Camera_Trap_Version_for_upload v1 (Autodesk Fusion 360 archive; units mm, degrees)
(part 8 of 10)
sketch "Sketch7" plane through (-24, 0, 0) normal (-1, 0, 0) x axis (0, -1, 0)
  line L1 (-21.6307, 110.325) -> (-21.6307, 118.7956)
  line L2 (-42.326, 110.325) -> (-21.6307, 110.325)
  line L3 (-42.326, 118.7956) -> (-42.326, 110.325)
  line L4 (-21.6307, 118.7956) -> (-42.326, 118.7956)
  line L5 (-18.3395, 176) -> (-20.9219, 176)
  line L6 (-44.3395, 176) -> (-46.9219, 176)
  curve K1 (35.395, 253.2053) -> (39.3474, 235.851)
  line L7 (-53, 253.2053) -> (35.395, 253.2053)
  line L8 (-53, 28) -> (-53, 253.2053)
  line L9 (-33, 28) -> (-53, 28)
  line L10 (-2.8201, 28) -> (-33, 28)
  line L11 (-35, 194) -> (-35, 213)
  line L12 (-42, 194) -> (-35, 194)
  line L13 (-42, 213) -> (-42, 194)
  line L14 (-35, 213) -> (-42, 213)
  arc A1 centre (-19.6307, 176.5411) radius 1.4 clockwise from (-18.3395, 176) to (-20.9219, 176)
  arc A2 centre (-45.6307, 176.5411) radius 1.4 clockwise from (-44.3395, 176) to (-46.9219, 176)
  circle C1 centre (-19.6307, 107.155) radius 1.4
  circle C2 centre (-45.6307, 107.155) radius 1.4
  arc A3 centre (-2.8201, 80) radius 52 clockwise from (40.4895, 108.7798) to (-2.8201, 28)
  arc A4 centre (82.1333, 136.4527) radius 50 clockwise from (40.4895, 108.7798) to (32.1436, 135.4388)
  arc A5 centre (1.7685, 134.8228) radius 30.3814 clockwise from (31.815, 139.3208) to (32.1436, 135.4388)
  arc A6 centre (81.264, 146.7234) radius 50 clockwise from (31.815, 139.3208) to (40.632, 175.8617)
  arc A7 centre (0, 205) radius 50 clockwise from (39.3474, 235.851) to (40.632, 175.8617)
extrude "Extrude18" add sketch "Sketch7" profile of L1 L2 L3 L4 against normal blind 5
extrude "Extrude19" add of existing geometry blind 6
extrude "Extrude20" add of existing geometry blind 2
move "Move1"
sketch "Sketch8" plane through (-24, 0, 0) normal (-1, 0, 0) x axis (0, -1, 0)
  line L1 (-18.3395, 176) -> (-20.9219, 176)
  line L2 (-44.3395, 176) -> (-46.9219, 176)
  curve K1 (35.395, 253.2053) -> (39.3474, 235.851)
  line L3 (-53, 253.2053) -> (35.395, 253.2053)
  line L4 (-53, 28) -> (-53, 253.2053)
  line L5 (-33, 28) -> (-53, 28)
  line L6 (-2.8201, 28) -> (-33, 28)
  line L7 (-35, 194) -> (-35, 213)
  line L8 (-42, 194) -> (-35, 194)
  line L9 (-42, 213) -> (-42, 194)
  line L10 (-35, 213) -> (-42, 213)
  line L11 (-14.5, 105.4339) -> (-50.5, 105.4339)
  line L12 (-50.5, 176) -> (-50.5, 105.4339)
  line L13 (-14.5, 176) -> (-50.5, 176)
  line L14 (-14.5, 105.4339) -> (-14.5, 176)
  curve K2 (-25.2655, 144.5781) -> (-27.9943, 141.8305)
  line L15 (-25.2773, 147.9781) -> (-25.2655, 144.5781)
  curve K3 (-28.0249, 150.7069) -> (-25.2773, 147.9781)
  line L16 (-31.5199, 150.6948) -> (-28.0249, 150.7069)
  curve K4 (-34.2486, 147.9471) -> (-31.5199, 150.6948)
  line L17 (-34.2369, 144.5472) -> (-34.2486, 147.9471)
  curve K5 (-31.4893, 141.8184) -> (-34.2369, 144.5472)
  line L18 (-27.9943, 141.8305) -> (-31.4893, 141.8184)
  curve K6 (-25.2925, 156.805) -> (-28.0307, 154.0668)
  line L19 (-25.2925, 160.205) -> (-25.2925, 156.805)
  curve K7 (-28.0307, 162.9432) -> (-25.2925, 160.205)
  line L20 (-31.5257, 162.9432) -> (-28.0307, 162.9432)
  curve K8 (-34.2639, 160.205) -> (-31.5257, 162.9432)
  line L21 (-34.2639, 156.805) -> (-34.2639, 160.205)
  curve K9 (-31.5257, 154.0668) -> (-34.2639, 156.805)
  line L22 (-28.0307, 154.0668) -> (-31.5257, 154.0668)
  arc A1 centre (-19.6307, 176.5411) radius 1.4 clockwise from (-18.3395, 176) to (-20.9219, 176)
  arc A2 centre (-45.6307, 176.5411) radius 1.4 clockwise from (-44.3395, 176) to (-46.9219, 176)
  arc A3 centre (-2.8201, 80) radius 52 clockwise from (40.4895, 108.7798) to (-2.8201, 28)
  arc A4 centre (82.1333, 136.4527) radius 50 clockwise from (40.4895, 108.7798) to (32.1436, 135.4388)
  arc A5 centre (1.7685, 134.8228) radius 30.3814 clockwise from (31.815, 139.3208) to (32.1436, 135.4388)
  arc A6 centre (81.264, 146.7234) radius 50 clockwise from (31.815, 139.3208) to (40.632, 175.8617)
  arc A7 centre (0, 205) radius 50 clockwise from (39.3474, 235.851) to (40.632, 175.8617)
move "Move2"
sketch "Sketch9" plane through (-24, 0, 0) normal (-1, 0, 0) x axis (0, -1, 0)
  line L1 (-18.3395, 176) -> (-20.9219, 176)
  line L2 (-44.3395, 176) -> (-46.9219, 176)
  curve K1 (35.395, 253.2053) -> (39.3474, 235.851)
  line L3 (-53, 253.2053) -> (35.395, 253.2053)
  line L4 (-53, 28) -> (-53, 253.2053)
  line L5 (-33, 28) -> (-53, 28)
  line L6 (-2.8201, 28) -> (-33, 28)
  line L7 (-35, 194) -> (-35, 213)
  line L8 (-42, 194) -> (-35, 194)
  line L9 (-42, 213) -> (-42, 194)
  line L10 (-35, 213) -> (-42, 213)
  line L11 (-14.5, 105.4339) -> (-14.5, 176)
  line L12 (-14.5, 176) -> (-50.5, 176)
  line L13 (-50.5, 176) -> (-50.5, 105.4339)
  line L14 (-14.5, 105.4339) -> (-50.5, 105.4339)
  arc A1 centre (-19.6307, 176.5411) radius 1.4 clockwise from (-18.3395, 176) to (-20.9219, 176)
  arc A2 centre (-45.6307, 176.5411) radius 1.4 clockwise from (-44.3395, 176) to (-46.9219, 176)
  arc A3 centre (-2.8201, 80) radius 52 clockwise from (40.4895, 108.7798) to (-2.8201, 28)
  arc A4 centre (82.1333, 136.4527) radius 50 clockwise from (40.4895, 108.7798) to (32.1436, 135.4388)
  arc A5 centre (1.7685, 134.8228) radius 30.3814 clockwise from (31.815, 139.3208) to (32.1436, 135.4388)
  arc A6 centre (81.264, 146.7234) radius 50 clockwise from (31.815, 139.3208) to (40.632, 175.8617)
  arc A7 centre (0, 205) radius 50 clockwise from (39.3474, 235.851) to (40.632, 175.8617)
extrude "Extrude21" cut sketch "Sketch2" against normal blind 3
sketch "Sketch10" plane through (-24, 0, 0) normal (-1, 0, 0) x axis (0, -1, 0)
  line L1 (-49, 173) -> (-49, 116.4339)
  line L2 (-16, 173) -> (-49, 173)
  line L3 (-16, 116.4339) -> (-16, 173)
  line L4 (-49, 116.4339) -> (-16, 116.4339)
  line L5 (-18.3395, 176) -> (-20.9219, 176)
  line L6 (-44.3395, 176) -> (-46.9219, 176)
  curve K1 (35.395, 253.2053) -> (39.3474, 235.851)
  line L7 (-53, 253.2053) -> (35.395, 253.2053)
  line L8 (-53, 28) -> (-53, 253.2053)
  line L9 (-33, 28) -> (-53, 28)
  line L10 (-2.8201, 28) -> (-33, 28)
  line L11 (-35, 194) -> (-35, 213)
  line L12 (-42, 194) -> (-35, 194)
  line L13 (-42, 213) -> (-42, 194)
  line L14 (-35, 213) -> (-42, 213)
  line L15 (-11.1732, 178.4668) -> (-50.2813, 178.4668)
  line L16 (-11.1732, 173) -> (-11.1732, 178.4668)
  line L17 (-50.2813, 173) -> (-11.1732, 173)
  line L18 (-50.2813, 178.4668) -> (-50.2813, 173)
  arc A1 centre (-19.6307, 176.5411) radius 1.4 clockwise from (-18.3395, 176) to (-20.9219, 176)
  arc A2 centre (-45.6307, 176.5411) radius 1.4 clockwise from (-44.3395, 176) to (-46.9219, 176)
  arc A3 centre (-2.8201, 80) radius 52 clockwise from (40.4895, 108.7798) to (-2.8201, 28)
  arc A4 centre (82.1333, 136.4527) radius 50 clockwise from (40.4895, 108.7798) to (32.1436, 135.4388)
  arc A5 centre (1.7685, 134.8228) radius 30.3814 clockwise from (31.815, 139.3208) to (32.1436, 135.4388)
  arc A6 centre (81.264, 146.7234) radius 50 clockwise from (31.815, 139.3208) to (40.632, 175.8617)
  arc A7 centre (0, 205) radius 50 clockwise from (39.3474, 235.851) to (40.632, 175.8617)
  horizontal L15
  vertical L16
  horizontal L17
  vertical L18
extrude "Extrude22" add of existing geometry blind 6
offset_faces "OffsetFaces2" distance -0.3
sketch "Sketch11" plane through (-24, 0, 0) normal (-1, 0, 0) x axis (0, -1, 0)
  line L1 (-35, 194) -> (-35, 213)
  line L2 (-42, 194) -> (-35, 194)
  line L3 (-42, 213) -> (-42, 194)
  line L4 (-35, 213) -> (-42, 213)
  curve K1 (35.395, 253.2053) -> (39.3474, 235.851)
  line L5 (-53, 253.2053) -> (35.395, 253.2053)
  line L6 (-53, 28) -> (-53, 253.2053)
  line L7 (-33, 28) -> (-53, 28)
  line L8 (-2.8201, 28) -> (-33, 28)
  line L9 (-49.3, 173.3) -> (-49.3, 116.1339)
  line L10 (-15.7, 173.3) -> (-49.3, 173.3)
  line L11 (-15.7, 116.1339) -> (-15.7, 173.3)
  line L12 (-49.3, 116.1339) -> (-15.7, 116.1339)
  line L13 (-41, 110.4339) -> (-22, 110.4339)
  line L14 (-22, 116.4339) -> (-22, 110.4339)
  line L15 (-41, 116.4339) -> (-41, 110.4339)
  line L16 (-21.9927, 116.4339) -> (-41, 116.4339)
  line L17 (-21.9927, 107.685) -> (-21.9927, 116.4339)
  line L18 (-41, 107.685) -> (-21.9927, 107.685)
  line L19 (-41, 116.4339) -> (-41, 107.685)
  arc A1 centre (-2.8201, 80) radius 52 clockwise from (40.4895, 108.7798) to (-2.8201, 28)
  arc A2 centre (82.1333, 136.4527) radius 50 clockwise from (40.4895, 108.7798) to (32.1436, 135.4388)
  arc A3 centre (1.7685, 134.8228) radius 30.3814 clockwise from (31.815, 139.3208) to (32.1436, 135.4388)
  arc A4 centre (81.264, 146.7234) radius 50 clockwise from (31.815, 139.3208) to (40.632, 175.8617)
  arc A5 centre (0, 205) radius 50 clockwise from (39.3474, 235.851) to (40.632, 175.8617)
  point P28 (-41, 116.4339)
  point P29 (-41, 116.4339)
  horizontal L16
  vertical L17
  horizontal L18
  vertical L19
  coincident P28 P29
extrude "Extrude23" cut sketch "Sketch11" profile of L12 L13 L14 L15 L17 L18 L19 to an object
move "Move3"
extrude "Extrude24" cut sketch "Sketch8" + "Sketch6" + "Sketch10" profile of S2:C1 S1:A1 S1:A2 S1:L11 S1:L12 S1:L13 S1:L14 S1:K2 S1:L15 S1:K3 S1:L16 S1:K4 S1:L17 S1:K5 S1:L18 S1:K6 S1:L19 S1:K7 S1:L20 S1:K8 S1:L21 S1:K9 S1:L22 S3:A2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 blind -3
extrude "Extrude25" cut of existing geometry to an object
extrude "Extrude26" cut of existing geometry to an object
sketch "Sketch12" plane through (-24, 0, 0) normal (-1, 0, 0) x axis (0, -1, 0)
  line L1 (-14.5, 105.4339) -> (-14.5, 176)
  line L2 (-50.5, 105.4339) -> (-14.5, 105.4339)
  line L3 (-50.5, 176) -> (-50.5, 105.4339)
  line L4 (-20.9219, 176) -> (-50.5, 176)
  line L5 (-14.5, 176) -> (-18.3395, 176)
  line L6 (-35, 194) -> (-35, 213)
  line L7 (-42, 194) -> (-35, 194)
  line L8 (-42, 213) -> (-42, 194)
  line L9 (-35, 213) -> (-42, 213)
  curve K1 (35.395, 253.2053) -> (39.3474, 235.851)
  line L10 (-53, 253.2053) -> (35.395, 253.2053)
  line L11 (-53, 28) -> (-53, 253.2053)
  line L12 (-33, 28) -> (-53, 28)
  line L13 (-2.8201, 28) -> (-33, 28)
  line L14 (-18.3395, 176) -> (-20.9219, 176)
  arc A1 centre (-19.6307, 176.5411) radius 1.4 clockwise from (-18.3395, 176) to (-20.9219, 176)
  arc A2 centre (-2.8201, 80) radius 52 clockwise from (40.4895, 108.7798) to (-2.8201, 28)
  arc A3 centre (82.1333, 136.4527) radius 50 clockwise from (40.4895, 108.7798) to (32.1436, 135.4388)
  arc A4 centre (1.7685, 134.8228) radius 30.3814 clockwise from (31.815, 139.3208) to (32.1436, 135.4388)
  arc A5 centre (81.264, 146.7234) radius 50 clockwise from (31.815, 139.3208) to (40.632, 175.8617)
  arc A6 centre (0, 205) radius 50 clockwise from (39.3474, 235.851) to (40.632, 175.8617)
  point P6 (-20.9219, 176)
  point P28 (-20.9219, 176)
  point P7 (-18.3395, 176)
  point P29 (-18.3395, 176)
  coincident P6 P28
  coincident P7 P29
extrude "Extrude27" cut sketch "Sketch12" profile of A1 L14 against normal blind 3
extrude "Extrude28" cut of existing geometry blind -1
extrude "Extrude29" cut of existing geometry blind -1
extrude "Extrude24" cut of existing geometry blind -3
fillet "Fillet1" radius 1
fillet "Fillet2" radius 1
fillet "Fillet3" radius 1
fillet "Fillet4" radius 1
fillet "Fillet1" radius 1
fillet "Fillet2" radius 1
fillet "Fillet3" radius 1
fillet "Fillet4" radius 1
extrude "Extrude24" cut of existing geometry to an object
extrude "Extrude25" cut of existing geometry blind -1
combine "Combine5"
sketch "Sketch33" plane through (-28.991, 0, 0) normal (-1, 0, 0) x axis (0, -1, 0)
  line L1 (-15.5, 105.4339) -> (-49.5, 105.4339)
  line L2 (-14.5, 175) -> (-14.5, 106.4339)
  line L3 (-49.5, 176) -> (-15.5, 176)
  line L4 (-50.5, 106.4339) -> (-50.5, 175)
  line L5 (-31.5257, 154.0668) -> (-28.0307, 154.0668)
  curve K1 (-34.2639, 156.805) -> (-31.5257, 154.0668)
  line L6 (-34.2639, 160.205) -> (-34.2639, 156.805)
  curve K2 (-31.5257, 162.9432) -> (-34.2639, 160.205)
  line L7 (-28.0307, 162.9432) -> (-31.5257, 162.9432)
  curve K3 (-25.2925, 160.205) -> (-28.0307, 162.9432)
  line L8 (-25.2925, 156.805) -> (-25.2925, 160.205)
  curve K4 (-28.0307, 154.0668) -> (-25.2925, 156.805)
  line L9 (-31.4893, 141.8184) -> (-27.9943, 141.8305)
  curve K5 (-34.2369, 144.5472) -> (-31.4893, 141.8184)
  line L10 (-34.2486, 147.9471) -> (-34.2369, 144.5472)
  curve K6 (-31.5199, 150.6948) -> (-34.2486, 147.9471)
  line L11 (-28.0249, 150.7069) -> (-31.5199, 150.6948)
  curve K7 (-25.2773, 147.9781) -> (-28.0249, 150.7069)
  line L12 (-25.2655, 144.5781) -> (-25.2773, 147.9781)
  curve K8 (-27.9943, 141.8305) -> (-25.2655, 144.5781)
  line L13 (-32.5, 105.4339) -> (-32.5, 176)
  line L14 (-50.5, 140.7169) -> (-14.5, 140.7169)
  arc A1 centre (-49.5, 106.4339) radius 1 clockwise from (-49.5, 105.4339) to (-50.5, 106.4339)
  arc A2 centre (-15.5, 106.4339) radius 1 clockwise from (-14.5, 106.4339) to (-15.5, 105.4339)
  arc A3 centre (-15.5, 175) radius 1 clockwise from (-15.5, 176) to (-14.5, 175)
  arc A4 centre (-49.5, 175) radius 1 clockwise from (-50.5, 175) to (-49.5, 176)
  circle C1 centre (-47, 109) radius 1
  circle C2 centre (-18, 109) radius 1
  circle C3 centre (-47, 172.4339) radius 1
  circle C4 centre (-18, 172.4339) radius 1
  point P30 (-32.5, 176)
  point P31 (-32.5, 105.4339)
  point P32 (-14.5, 140.7169)
  point P33 (-50.5, 140.7169)
  point P34 (-47, 109)
  point P36 (-47, 172.4339)
  point P37 (-47, 172.4339)
  midpoint L3 P30
  midpoint L1 P31
  midpoint L2 P32
  midpoint L4 P33
  symmetric L13 C1 C2
  symmetric L14 P34 P36
  coincident P36 P37
  symmetric L13 C3 C4
  dimension "d1688" diameter C1 = 2
  dimension "d1689" diameter C3 = 2
extrude "Extrude30" cut sketch "Sketch33" profile of C1 C2 C3 C4 against normal blind 9
sketch "Sketch34" plane through (-17, 0, 0) normal (1, 0, 0) x axis (0, 1, 0)
  line L1 (33, 28) -> (2.8201, 28)
  line L2 (53, 28) -> (33, 28)
  line L3 (53, 253.2053) -> (53, 28)
  line L4 (-35.395, 253.2053) -> (53, 253.2053)
  curve K1 (-35.395, 253.2053) -> (-39.3474, 235.851)
  line L5 (13.4103, 132.8522) -> (13.4103, 142.8522)
  line L6 (-11.9897, 142.8522) -> (-11.9897, 132.8522)
  line L7 (35, 213) -> (35, 194)
  line L8 (42, 213) -> (35, 213)
  line L9 (42, 194) -> (42, 213)
  line L10 (35, 194) -> (42, 194)
  line L11 (41, 105.685) -> (41, 116.1339)
  line L12 (21.9927, 105.685) -> (41, 105.685)
  line L13 (21.9927, 116.1339) -> (21.9927, 105.685)
  line L14 (41, 116.1339) -> (21.9927, 116.1339)
  circle C1 centre (-38.4779, 196.3786) radius 5.075
  circle C2 centre (-38.4779, 86.3786) radius 5.075
  circle C3 centre (0.7043, 203.169) radius 13.1
  arc A1 centre (2.8201, 80) radius 52 clockwise from (2.8201, 28) to (-40.4895, 108.7798)
  arc A2 centre (0, 205) radius 50 clockwise from (-40.632, 175.8617) to (-39.3474, 235.851)
  arc A3 centre (-81.264, 146.7234) radius 50 clockwise from (-40.632, 175.8617) to (-31.815, 139.3208)
  arc A4 centre (-1.7685, 134.8228) radius 30.3814 clockwise from (-32.1436, 135.4388) to (-31.815, 139.3208)
  arc A5 centre (-82.1333, 136.4527) radius 50 clockwise from (-32.1436, 135.4388) to (-40.4895, 108.7798)
  circle C4 centre (51, 205) radius 1.5
  circle C5 centre (0.6307, 70.355) radius 13.1
  arc A6 centre (0.7103, 132.8522) radius 12.7 clockwise from (13.4103, 132.8522) to (-11.9897, 132.8522)
  arc A7 centre (0.7103, 142.8522) radius 12.7 clockwise from (-11.9897, 142.8522) to (13.4103, 142.8522)
combine "Combine1" bodies "Back_wall"
offset_faces "OffsetFaces1" distance 20
sketch "Sketch1" plane through (0, 53, 0) normal (0, -1, 0) x axis (1, 0, 0)
  line L1 (-17, 285.3985) -> (77.3814, 285.3985)
  line L2 (-17, 253.2053) -> (-17, 285.3985)
  line L3 (-24, 253.2053) -> (-17, 253.2053)
  line L4 (-24, 253.2048) -> (-24, 253.2053)
  line L5 (77.3814, 253.2048) -> (-24, 253.2048)
  line L6 (77.3814, 285.3985) -> (77.3814, 253.2048)
  line L7 (60.8674, 243.2048) -> (60.8674, 253.2048)
  line L8 (49.8805, 243.2048) -> (49.8805, 253.2048)
  circle C1 centre (55.374, 243.2048) radius 5.4934
  circle C2 centre (55.374, 243.2048) radius 1.5
  point P8 (60.8674, 253.2048)
  point P10 (49.8805, 253.2048)
  point P11 (49.8805, 243.2048)
  point P9 (60.8674, 243.2048)
  coincident L5 P8
  perpendicular L5 L7
  coincident L5 P10
  perpendicular L5 L8
  coincident P11 C1
  tangent L8 C1
  coincident P9 C1
  concentric C1 C2
  dimension "d1697" distance P8 P9 = 10
  dimension "d1698" distance P10 P11 = 10
  dimension "d1699" diameter C2 = 3
extrude "Extrude1" new body sketch "Sketch1" profile of L5 L7 L8 C1 C2 along normal blind 2
offset_faces "OffsetFaces2" distance 1
draft "Draft1" Angle1 40 Angle2 0
combine "Combine1"
sketch "Sketch2" plane through (125, 0, 0) normal (-1, 0, 0) x axis (0, -1, 0)
  line L1 (-53, 253.2053) -> (-53, 285.3985)
  line L2 (65.2611, 253.2053) -> (-53, 253.2053)
  line L3 (-53, 285.3985) -> (65.2611, 253.2053)
  line L4 (-4.7389, 253.2053) -> (65.2611, 253.2053)
  line L5 (-4.7389, 243.2053) -> (-4.7389, 253.2053)
  line L6 (-13.6775, 243.2053) -> (-13.6775, 253.2053)
  circle C1 centre (-6.6916, 266.9657) radius 3.15
  circle C2 centre (-9.2082, 243.2053) radius 4.4693
  circle C3 centre (-9.2082, 243.2053) radius 1.5
  point P4 (65.2611, 253.2053)
  point P6 (65.2611, 253.2053)
  point P9 (-13.6775, 253.2053)
  point P10 (-13.6775, 243.2053)
  point P8 (-4.7389, 243.2053)
  point P7 (-4.7389, 253.2053)
  coincident P4 P6
  parallel L2 L4
  perpendicular L2 L5
  coincident L2 P9
  perpendicular L2 L6
  coincident P10 C2
  tangent L6 C2
  coincident P8 C2
  concentric C2 C3
  dimension "d1705" distance P6 P7 = 70
  dimension "d1706" distance P7 P8 = 10
  dimension "d1707" distance P9 P10 = 10
  dimension "d1708" diameter C3 = 3
extrude "Extrude2" new body sketch "Sketch2" profile of L2 L5 L6 C2 C3 along normal blind 2
draft "Draft2" Angle1 45 Angle2 0
combine "Combine2"
sketch "Sketch3" plane through (-17, 0, 0) normal (1, 0, 0) x axis (0, 1, 0)
  line L1 (53, 253.2053) -> (-65.2611, 253.2053)
  line L2 (53, 285.3985) -> (53, 253.2053)
  line L3 (-65.2611, 253.2053) -> (53, 285.3985)
  line L4 (4.7389, 253.2053) -> (-65.2611, 253.2053)
  line L5 (4.7389, 243.2053) -> (4.7389, 253.2053)
  line L6 (4.7389, 253.2053) -> (13.6775, 253.2053)
  line L7 (4.7389, 243.2053) -> (4.7389, 253.2053)
  line L8 (13.6775, 253.2053) -> (13.6775, 243.2053)
  line L9 (13.6775, 243.2053) -> (13.6775, 253.2053)
  arc A1 centre (9.2082, 243.2053) radius 4.4693 clockwise from (13.6775, 243.2053) to (4.7389, 243.2053)
  circle C1 centre (9.2082, 243.2053) radius 1.5
  circle C2 centre (9.2082, 243.2053) radius 4.4693
  circle C3 centre (9.2082, 243.2053) radius 1.5
  point P2 (-65.2611, 253.2053)
  point P5 (-65.2611, 253.2053)
  point P8 (13.6775, 253.2053)
  point P13 (13.6775, 253.2053)
  point P11 (13.6775, 243.2053)
  point P14 (13.6775, 243.2053)
  point P7 (4.7389, 243.2053)
  point P6 (4.7389, 253.2053)
  coincident P2 P5
  parallel L1 L4
  perpendicular L1 L5
  coincident P8 P13
  coincident P11 P14
  coincident P7 C2
  tangent L7 C2
  coincident P11 C2
  concentric A1 C3
  dimension "d1713" distance P5 P6 = 70
  dimension "d1714" distance P6 P7 = 10
  dimension "d1715" diameter C3 = 3
extrude "Extrude3" new body sketch "Sketch3" profile of L1 L5 L6 L7 A1 L8 C1 L9 C2 C3 along normal blind 2
draft "Draft3" Angle1 50 Angle2 0
combine "Combine3"
offset_faces "OffsetFaces3" distance -30
offset_faces "OffsetFaces4" distance -45
offset_faces "OffsetFaces5" distance -45
sketch "Sketch4" plane through (0, -68.6749, 252.2759) normal (0, 0.2627, -0.9649) x axis (-1, 0, 0)
  line L1 (22, -102.5732) -> (-130, -102.5732)
  line L2 (22, 3.5381) -> (22, -102.5732)
  line L3 (17, 3.5381) -> (22, 3.5381)
  line L4 (17, 126.1027) -> (17, 3.5381)
  line L5 (-77.3814, 126.1027) -> (17, 126.1027)
  line L6 (-77.3814, -93.8973) -> (-77.3814, 126.1027)
  line L7 (-97.3814, -93.8973) -> (-77.3814, -93.8973)
  line L8 (-97.3814, 126.1027) -> (-97.3814, -93.8973)
  line L9 (-125, 126.1027) -> (-97.3814, 126.1027)
  line L10 (-125, 3.5381) -> (-125, 126.1027)
  line L11 (-130, 3.5381) -> (-125, 3.5381)
  line L12 (-130, -102.5732) -> (-130, 3.5381)
  circle C1 centre (-101.5356, 117.6424) radius 1
  circle C2 centre (-101.5356, -50.4038) radius 1
  circle C3 centre (-54, -71.4746) radius 1
  circle C4 centre (-101.5356, -9.2833) radius 1
  circle C5 centre (-101.5356, 78.3036) radius 1
  circle C6 centre (-54, -52.5645) radius 1
  circle C7 centre (-54, -64) radius 1
  circle C8 centre (-101.5356, 31) radius 1
  circle C9 centre (-101.5356, -88.0171) radius 1
  circle C10 centre (-54, -84.4448) radius 1
  circle C11 centre (-54, -95.757) radius 1
  circle C12 centre (-71.0487, -95.757) radius 1
  circle C13 centre (-71.0487, -84.4448) radius 1
  dimension "d1723" diameter C9 = 2
  dimension "d1724" diameter C10 = 2
  dimension "d1725" diameter C11 = 2
  dimension "d1726" diameter C12 = 2
  dimension "d1727" diameter C13 = 2
extrude "Extrude4" cut sketch "Sketch4" profile of C9 C10 C11 C12 C13 against normal blind 4
position "Position38"
position "Position39"
position "Position40"
position "Position41"
sketch "LL_pin" plane through (0, 0, 0) normal (0, 1, 0) x axis (1, 0, 0)
  line L1 (200, 0) -> (-200, 0)
  line L2 (0, -70) -> (0, 0)
  line L3 (-11, -70) -> (5, -70)
  line L4 (-11, -74.1) -> (-11, -70)
  line L5 (5, -70) -> (5, -74.1)
  line L6 (-5, -70) -> (-3, -70)
  line L7 (-5, -75) -> (-5, -74.1)
  line L8 (-3, -75) -> (-5, -75)
  line L9 (-3, -74.1) -> (-3, -75)
  line L10 (-5, -74.1) -> (-11, -74.1)
  line L11 (5, -74.1) -> (-3, -74.1)
  point P1 (0, 0)
  point P4 (0, 0)
  point P10 (-3, -70)
  point P2 (-200, 0)
  point P3 (200, 0)
  point P5 (0, -70)
  point P6 (5, -70)
  point P7 (-11, -70)
  point P9 (5, -74.1)
  point P11 (-5, -70)
  point P13 (-3, -75)
  horizontal L1
  coincident P1 P4
  perpendicular L1 L2
  horizontal L3
  vertical L4
  horizontal L10
  vertical L5
  horizontal L6
  vertical L7
  horizontal L8
  vertical L9
  midpoint L3 P10
  collinear L10 L11
  dimension "d120_2_1" distance P2 P3 = 400
  dimension "d122_2_1" distance P4 P5 = 70
  dimension "d123_2_1" distance P6 P7 = 16 (= "LL_Pin_Length")
  dimension "d124_2_1" distance P6 P9 = 4.1 (= "LL_Pin_half_height")
  dimension "d129_2_1" distance P10 P11 = 2 (= "LL_lip_length")
  dimension "d130_2_1" distance P10 P13 = 5 (= "LL_lip_half_height")
revolve "Revolve1" sketch "LL_pin" AlongAngle 360 named "d131_2_1" bodies "S1_L_Pin"
sketch "LL_pin_falt_face" plane through (5, 0, 0) normal (1, 0, 0) x axis (0, 1, 0)
  line L1 (0, 67) -> (0, 70)
  line L2 (2.8039, 67.0087) -> (-2.8039, 67.0087)
  circle C1 centre (0, 70) radius 4.1
  point P2 (0, 70)
  point P3 (0, 70)
  point P5 (-2.8039, 67.0087)
  point P6 (2.8039, 67.0087)
  coincident P2 P3
  vertical L1
  coincident C1 P5
  coincident C1 P6
  perpendicular L1 L2
extrude "Extrude1" cut sketch "LL_pin_falt_face" profile of C1 L2 against normal blind 5 named "d132_2_1"
fillet "Fillet1" radius 1 named "d135_2_1"
sketch "paper_holder" plane through (0, 0, 0) normal (0, 1, 0) x axis (1, 0, 0)
  line L1 (16, -74.1) -> (16, -77.5)
  line L2 (11, -74.1) -> (16, -74.1)
  line L3 (11, -70) -> (11, -74.1)
  line L4 (127, -75) -> (129, -75)
  line L5 (127, -77.5) -> (127, -75)
  line L6 (16, -77.5) -> (127, -77.5)
  line L7 (135, -74.1) -> (135, -70)
  line L8 (129, -74.1) -> (135, -74.1)
  line L9 (129, -75) -> (129, -74.1)
  line L10 (150, -70) -> (140, -70)
  line L11 (135, -70) -> (11, -70)
  line L12 (21, -74.1) -> (16, -74.1)
  line L13 (122, -69) -> (122, -71)
  line L14 (21, -71) -> (21, -69)
  line L15 (122, -80) -> (21, -80)
  line L16 (122, -62.5) -> (122, -80)
  line L17 (21, -62.5) -> (122, -62.5)
  line L18 (21, -80) -> (21, -62.5)
  point P2 (16, -77.5)
  point P3 (16, -74.1)
  point P4 (11, -74.1)
  point P5 (129, -75)
  point P6 (127, -75)
  point P7 (127, -77.5)
  point P15 (21, -71)
  point P16 (122, -71)
  point P19 (21, -80)
  point P20 (122, -80)
  point P22 (21, -62.5)
  vertical L1
  perpendicular L1 L2
  perpendicular L2 L3
  perpendicular L4 L5
  parallel L8 L10
  perpendicular L1 L12
  vertical L13
  vertical L14
  horizontal L15
  vertical L16
  horizontal L17
  vertical L18
  dimension "d146_1_1" distance P2 P3 = 3.4
  dimension "d147_1_1" distance P3 P4 = 5
  dimension "d154_1_1" distance P5 P6 = 2
  dimension "d155_1_1" distance P6 P7 = 2.5
  dimension "d164_1_1" distance P15 P16 = 101
  dimension "d167_1_1" distance P19 P20 = 101
  dimension "d168_1_1" distance P19 P22 = 17.5
revolve "Revolve1" sketch "paper_holder" AlongAngle 360 named "d159_1_1" bodies "S1_paper_holder"
sketch "cutting_Base" plane through (127, 0, 0) normal (1, 0, 0) x axis (0, 1, 0)
  line L1 (2.3976, 62.8936) -> (-2.3976, 62.8936)
  circle C1 centre (0, 70) radius 5
  circle C2 centre (0, 70) radius 7.5
  point P3 (-2.3976, 62.8936)
  point P4 (2.3976, 62.8936)
  coincident C2 P3
  coincident C2 P4
  horizontal L1
extrude "Extrude1" cut sketch "cutting_Base" profile of C2 L1 against normal blind 110.1 named "d160_1_1"
extrude "Extrude3" cut sketch "paper_holder" profile of L6 L11 L13 L14 L15 L16 L17 L18 distance 1 named "d169_1_1"
remove_instance "RemoveInstance1"
sketch "flat_front_pin_base" plane through (11, 0, 0) normal (-1, 0, 0) x axis (0, -1, 0)
  line L1 (0, 70) -> (0, 74.1)
  line L2 (0, 67) -> (0, 70)
  line L3 (2.7971, 67.0023) -> (-2.7971, 67.0023)
  circle C1 centre (0, 70) radius 4.1
  point P3 (0, 74.1)
  point P2 (0, 70)
  point P4 (0, 70)
  point P5 (0, 70)
  point P7 (-2.7971, 67.0023)
  point P8 (2.7971, 67.0023)
  point P6 (0, 67)
  coincident C1 P3
  coincident P2 P4
  vertical L1
  coincident P2 P5
  parallel L1 L2
  coincident C1 P7
  coincident C1 P8
  horizontal L3
  dimension "d175_1_1" distance P5 P6 = 3
extrude "Extrude4" cut sketch "flat_front_pin_base" profile of C1 against normal blind 5 named "d173_1_1"
position "Position42"
position "Position43"
position "Position44"
position "Position45"
position "Position46"
sketch "Sketch8" plane through (15.8987, 0, 0) normal (-1, 0, 0) x axis (0, -1, 0)
  line L1 (-2.4466, 67.2087) -> (3.1475, 67.2087)
  line L2 (7.4918, 70.2065) -> (0.3505, 70.2065)
  line L3 (7.5159, 70.7065) -> (7.5159, 70.2065)
  line L4 (6.5159, 70.7065) -> (7.5159, 70.7065)
  line L5 (6.5159, 69.7065) -> (6.5159, 70.7065)
  line L6 (7.5159, 69.7) -> (7.5159, 70.2065)
  line L7 (7.5159, 69.7065) -> (6.5159, 69.7065)
  circle C1 centre (0.3505, 70.2065) radius 7.5
  arc A1 centre (0.3505, 70.2065) radius 4.1 clockwise from (-2.4466, 67.2087) to (3.1475, 67.2087)
  circle C2 centre (0, 70) radius 7.4947
  point P2 (0.3505, 70.2065)
  point P6 (0.3505, 70.2065)
  point P7 (7.4918, 70.2065)
  point P13 (7.5159, 69.7065)
  point P8 (7.5159, 70.2065)
  point P9 (7.5159, 70.7065)
  point P10 (6.5159, 70.7065)
  point P11 (6.5159, 69.7065)
  coincident P2 P6
  coincident C2 P7
  horizontal L2
  perpendicular L2 L3
  perpendicular L3 L4
  perpendicular L4 L5
  parallel L3 L6
  coincident L6 P13
  perpendicular L6 L7
  dimension "d1731" distance P8 P9 = 0.5
  dimension "d1732" distance P9 P10 = 1
  dimension "d1733" distance P10 P11 = 1
extrude "Extrude6" cut sketch "Sketch8" profile of C2 L2 L3 L4 L5 L6 L7 against normal blind 1
position "Position47"
sketch "LL_pin" plane through (0, 0, 0) normal (0, 1, 0) x axis (1, 0, 0)
  line L1 (200, 0) -> (-200, 0)
  line L2 (0, -70) -> (0, 0)
  line L3 (-11, -70) -> (5, -70)
  line L4 (-11, -74.1) -> (-11, -70)
  line L5 (5, -70) -> (5, -74.1)
  line L6 (-5, -70) -> (-3, -70)
  line L7 (-5, -75) -> (-5, -74.1)
  line L8 (-3, -75) -> (-5, -75)
  line L9 (-3, -74.1) -> (-3, -75)
  line L10 (-5, -74.1) -> (-11, -74.1)
  line L11 (5, -74.1) -> (-3, -74.1)
  point P1 (0, 0)
  point P4 (0, 0)
  point P10 (-3, -70)
  point P2 (-200, 0)
  point P3 (200, 0)
  point P5 (0, -70)
  point P6 (5, -70)
  point P7 (-11, -70)
  point P9 (5, -74.1)
  point P11 (-5, -70)
  point P13 (-3, -75)
  horizontal L1
  coincident P1 P4
  perpendicular L1 L2
  horizontal L3
  vertical L4
  horizontal L10
  vertical L5
  horizontal L6
  vertical L7
  horizontal L8
  vertical L9
  midpoint L3 P10
  collinear L10 L11
  dimension "d120_2_2" distance P2 P3 = 400
  dimension "d122_2_2" distance P4 P5 = 70
  dimension "d123_2_2" distance P6 P7 = 16 (= "LL_Pin_Length")
  dimension "d124_2_2" distance P6 P9 = 4.1 (= "LL_Pin_half_height")
  dimension "d129_2_2" distance P10 P11 = 2 (= "LL_lip_length")
  dimension "d130_2_2" distance P10 P13 = 5 (= "LL_lip_half_height")
revolve "Revolve1" sketch "LL_pin" AlongAngle 360 named "d131_2_2" bodies "S1_L_Pin"
sketch "LL_pin_falt_face" plane through (5, 0, 0) normal (1, 0, 0) x axis (0, 1, 0)
  line L1 (0, 67) -> (0, 70)
  line L2 (2.8039, 67.0087) -> (-2.8039, 67.0087)
  circle C1 centre (0, 70) radius 4.1
  point P2 (0, 70)
  point P3 (0, 70)
  point P5 (-2.8039, 67.0087)
  point P6 (2.8039, 67.0087)
  coincident P2 P3
  vertical L1
  coincident C1 P5
  coincident C1 P6
  perpendicular L1 L2
extrude "Extrude1" cut sketch "LL_pin_falt_face" profile of C1 L2 against normal blind 5 named "d132_2_2"
fillet "Fillet1" radius 1 named "d135_2_2"
sketch "paper_holder" plane through (0, 0, 0) normal (0, 1, 0) x axis (1, 0, 0)
  line L1 (16, -74.1) -> (16, -77.5)
  line L2 (11, -74.1) -> (16, -74.1)
  line L3 (11, -70) -> (11, -74.1)
  line L4 (127, -75) -> (129, -75)
  line L5 (127, -77.5) -> (127, -75)
  line L6 (16, -77.5) -> (127, -77.5)
  line L7 (135, -74.1) -> (135, -70)
  line L8 (129, -74.1) -> (135, -74.1)
  line L9 (129, -75) -> (129, -74.1)
  line L10 (150, -70) -> (140, -70)
  line L11 (135, -70) -> (11, -70)
  line L12 (21, -74.1) -> (16, -74.1)
  line L13 (122, -69) -> (122, -71)
  line L14 (21, -71) -> (21, -69)
  line L15 (122, -80) -> (21, -80)
  line L16 (122, -62.5) -> (122, -80)
  line L17 (21, -62.5) -> (122, -62.5)
  line L18 (21, -80) -> (21, -62.5)
  point P2 (16, -77.5)
  point P3 (16, -74.1)
  point P4 (11, -74.1)
  point P5 (129, -75)
  point P6 (127, -75)
  point P7 (127, -77.5)
  point P15 (21, -71)
  point P16 (122, -71)
  point P19 (21, -80)
  point P20 (122, -80)
  point P22 (21, -62.5)
  vertical L1
  perpendicular L1 L2
  perpendicular L2 L3
  perpendicular L4 L5
  parallel L8 L10
  perpendicular L1 L12
  vertical L13
  vertical L14
  horizontal L15
  vertical L16
  horizontal L17
  vertical L18
  dimension "d146_1_2" distance P2 P3 = 3.4
  dimension "d147_1_2" distance P3 P4 = 5
  dimension "d154_1_2" distance P5 P6 = 2
  dimension "d155_1_2" distance P6 P7 = 2.5
  dimension "d164_1_2" distance P15 P16 = 101
  dimension "d167_1_2" distance P19 P20 = 101
  dimension "d168_1_2" distance P19 P22 = 17.5
revolve "Revolve1" sketch "paper_holder" AlongAngle 360 named "d159_1_2" bodies "S1_paper_holder"
sketch "cutting_Base" plane through (127, 0, 0) normal (1, 0, 0) x axis (0, 1, 0)
  line L1 (2.3976, 62.8936) -> (-2.3976, 62.8936)
  circle C1 centre (0, 70) radius 5
  circle C2 centre (0, 70) radius 7.5
  point P3 (-2.3976, 62.8936)
  point P4 (2.3976, 62.8936)
  coincident C2 P3
  coincident C2 P4
  horizontal L1
extrude "Extrude1" cut sketch "cutting_Base" profile of C2 L1 against normal blind 110.1 named "d160_1_2"
extrude "Extrude3" cut sketch "paper_holder" profile of L6 L11 L13 L14 L15 L16 L17 L18 distance 1 named "d169_1_2"
remove_instance "RemoveInstance1"
sketch "flat_front_pin_base" plane through (11, 0, 0) normal (-1, 0, 0) x axis (0, -1, 0)
  line L1 (0, 70) -> (0, 74.1)
  line L2 (0, 67) -> (0, 70)
  line L3 (2.7971, 67.0023) -> (-2.7971, 67.0023)
  circle C1 centre (0, 70) radius 4.1
  point P3 (0, 74.1)
  point P2 (0, 70)
  point P4 (0, 70)
  point P5 (0, 70)
  point P7 (-2.7971, 67.0023)
  point P8 (2.7971, 67.0023)
  point P6 (0, 67)
  coincident C1 P3
  coincident P2 P4
  vertical L1
  coincident P2 P5
  parallel L1 L2
  coincident C1 P7
  coincident C1 P8
  horizontal L3
  dimension "d175_1_2" distance P5 P6 = 3
extrude "Extrude4" cut sketch "flat_front_pin_base" profile of C1 against normal blind 5 named "d173_1_2"
position "Position48"
position "Position49"
position "Position50"
position "Position51"
extrude "Extrude5" cut sketch "Sketch8" profile of C2 L2 L3 L4 L5 L6 L7 against normal blind 1 named "d1736_1"
sketch "Sketch3" plane through (16, 0, 0) normal (1, 0, 0) x axis (0, 1, 0)
  line L1 (-2.5913, 66.7958) -> (3.2922, 66.7958)
  line L2 (-6.1655, 70.5) -> (-7.1162, 70.5)
  line L3 (-6.1655, 69.5) -> (-6.1655, 70.5)
  line L4 (-7.1438, 69.5) -> (-6.1655, 69.5)
  line L5 (-7.4829, 69.5) -> (-6.1655, 69.5)
  line L6 (-7.4829, 70.5058) -> (-7.4829, 69.5)
  line L7 (-6.1655, 70.5058) -> (-7.4829, 70.5058)
  line L8 (-6.1655, 69.5) -> (-6.1655, 70.5058)
  line L9 (-7.7, 69.5) -> (-6.1655, 69.5)
  line L10 (-7.7, 70.5) -> (-7.7, 69.5)
  line L11 (-6.1655, 70.5) -> (-7.7, 70.5)
  line L12 (-6.1655, 69.5) -> (-6.1655, 70.5)
  arc A1 centre (0.3505, 69.7935) radius 4.2 clockwise from (-2.5913, 66.7958) to (3.2922, 66.7958)
  circle C1 centre (0, 70) radius 7.5
  arc A2 centre (0.3505, 69.7935) radius 7.5 clockwise from (-7.1438, 69.5) to (-7.1162, 70.5)
  point P13 (-7.4829, 70.5058)
  point P10 (-6.1655, 69.5)
  point P11 (-6.1655, 69.5)
  point P15 (-6.1655, 69.5)
  horizontal L5
  vertical L6
  horizontal L7
  vertical L8
  coincident C1 P13
  coincident P10 P11
  horizontal L9
  vertical L10
  horizontal L11
  vertical L12
  coincident P10 P15
sketch "Sketch2" plane through (16, 0, 0) normal (1, 0, 0) x axis (0, 1, 0)
  line L1 (-7.6, 69.4999) -> (-6.1654, 69.4999)
  line L2 (-7.6, 70.5) -> (-7.6, 69.4999)
  line L3 (-6.1654, 70.5) -> (-7.6, 70.5)
  line L4 (-6.1654, 69.4999) -> (-6.1654, 70.5)
  horizontal L1
  vertical L2
  horizontal L3
  vertical L4
extrude "Extrude2" cut sketch "Sketch2" against normal blind 1
extrude "Extrude1" cut sketch "Sketch3" profile of A2 L2 L3 L4 L5 L6 L8 L9 L11 L12 against normal blind 1
extrude "Extrude2" cut of existing geometry blind -0.1
sketch "Sketch1" plane through (125.1507, 0, 0) normal (-1, 0, 0) x axis (0, -1, 0)
  line L1 (-53, 28) -> (-53, 30)
  line L2 (-53, 27.8784) -> (-53, 28)
  line L3 (-33.272, 27.8784) -> (-53, 27.8784)
  line L4 (-3.0921, 27.8784) -> (-33.272, 27.8784)
  curve K1 (35.123, 253.0837) -> (39.0754, 235.7294)
  line L5 (-53, 253.0837) -> (35.123, 253.0837)
  line L6 (-53, 30) -> (-53, 253.0837)
  line L7 (-41.272, 134.8784) -> (-41.272, 126.8784)
  line L8 (-46.8389, 134.8784) -> (-41.272, 134.8784)
  line L9 (-46.8389, 144.8784) -> (-46.8389, 134.8784)
  line L10 (9.728, 158.4453) -> (-33.272, 158.4453)
  line L11 (23.2949, 126.8784) -> (23.2949, 144.8784)
  line L12 (-33.272, 113.3115) -> (9.728, 113.3115)
  line L13 (-40.272, 115.9212) -> (-41.272, 115.9212)
  line L14 (-40.272, 123.0054) -> (-40.272, 115.9212)
  curve K2 (26.8076, 53.2945) -> (0.9867, 100.4527)
  curve K3 (-28.484, 81.7459) -> (3.2007, 38.3098)
  curve K4 (35.1296, 201.1524) -> (35.4896, 190.2254)
  curve K5 (41.4661, 190.2254) -> (41.8261, 201.1524)
  curve K6 (35.1296, 91.1524) -> (35.4896, 80.2254)
  curve K7 (41.4661, 80.2254) -> (41.8261, 91.1524)
  line L15 (24.3693, 188.2333) -> (24.3693, 218.2333)
  line L16 (-15.6307, 178.2333) -> (14.3693, 178.2333)
  line L17 (-25.6307, 218.2333) -> (-25.6307, 188.2333)
  line L18 (14.3693, 228.2333) -> (-15.6307, 228.2333)
  arc A1 centre (-3.0921, 79.8784) radius 52 clockwise from (40.2175, 108.6582) to (-3.0921, 27.8784)
  arc A2 centre (81.8613, 136.3311) radius 50 clockwise from (40.2175, 108.6582) to (31.8716, 135.3172)
  arc A3 centre (1.4965, 134.7011) radius 30.3814 clockwise from (31.543, 139.1992) to (31.8716, 135.3172)
  arc A4 centre (80.992, 146.6018) radius 50 clockwise from (31.543, 139.1992) to (40.36, 175.7401)
  arc A5 centre (-0.272, 204.8784) radius 50 clockwise from (39.0754, 235.7294) to (40.36, 175.7401)
  arc A6 centre (-33.272, 144.8784) radius 13.5669 clockwise from (-46.8389, 144.8784) to (-33.272, 158.4453)
  arc A7 centre (9.728, 144.8784) radius 13.5669 clockwise from (9.728, 158.4453) to (23.2949, 144.8784)
  arc A8 centre (9.728, 126.8784) radius 13.5669 clockwise from (23.2949, 126.8784) to (9.728, 113.3115)
  arc A9 centre (-33.272, 126.8784) radius 13.5669 clockwise from (-33.272, 113.3115) to (-41.272, 115.9212)
  arc A10 centre (-33.272, 126.8784) radius 8 clockwise from (-40.272, 123.0054) to (-41.272, 126.8784)
  arc A11 centre (-0.6307, 70.4333) radius 32.3513 clockwise from (26.8076, 53.2945) to (3.2007, 38.3098)
  arc A12 centre (-0.6307, 70.4333) radius 30.0629 clockwise from (-28.484, 81.7459) to (0.9867, 100.4527)
  arc A13 centre (38.4779, 196.4569) radius 5.767 clockwise from (35.1296, 201.1524) to (41.8261, 201.1524)
  arc A14 centre (38.4779, 196.4569) radius 6.911 clockwise from (41.4661, 190.2254) to (35.4896, 190.2254)
  arc A15 centre (38.4779, 86.4569) radius 5.767 clockwise from (35.1296, 91.1524) to (41.8261, 91.1524)
  arc A16 centre (38.4779, 86.4569) radius 6.911 clockwise from (41.4661, 80.2254) to (35.4896, 80.2254)
  arc A17 centre (14.3693, 188.2333) radius 10 clockwise from (24.3693, 188.2333) to (14.3693, 178.2333)
  arc A18 centre (-15.6307, 188.2333) radius 10 clockwise from (-15.6307, 178.2333) to (-25.6307, 188.2333)
  arc A19 centre (-15.6307, 218.2333) radius 10 clockwise from (-25.6307, 218.2333) to (-15.6307, 228.2333)
  arc A20 centre (14.3693, 218.2333) radius 10 clockwise from (14.3693, 228.2333) to (24.3693, 218.2333)
sketch "Sketch13" plane through (120, 0, 0) normal (-1, 0, 0) x axis (0, -1, 0)
  line L1 (-34, 164) -> (-42, 164)
  line L2 (-34, 158) -> (-34, 164)
  line L3 (-31, 158) -> (-34, 158)
  line L4 (-31, 245) -> (-31, 158)
  line L5 (-34, 245) -> (-31, 245)
  line L6 (-34, 239) -> (-34, 245)
  line L7 (-42, 239) -> (-34, 239)
  line L8 (-42, 245) -> (-42, 239)
  line L9 (-47.6, 245) -> (-42, 245)
  line L10 (-47.6, 248) -> (-47.6, 245)
  line L11 (-53, 248) -> (-47.6, 248)
  line L12 (-53, 158) -> (-53, 248)
  line L13 (-42, 158) -> (-53, 158)
  line L14 (-42, 164) -> (-42, 158)
  line L15 (-34.081, 207.919) -> (-39.919, 202.081)
  line L16 (-39.919, 207.919) -> (-34.081, 202.081)
  line L17 (-42, 207.5) -> (-35.5, 207.5)
  line L18 (-42, 202.5) -> (-42, 207.5)
  line L19 (-35.5, 202.5) -> (-42, 202.5)
  line L20 (-35.5, 207.5) -> (-35.5, 202.5)
  line L21 (-42, 220) -> (-42, 205)
  line L22 (-43, 220) -> (-42, 220)
  line L23 (-41.5, 190) -> (-43, 190)
  line L24 (-44.5465, 220) -> (-42, 220)
  line L25 (-44.5465, 190) -> (-44.5465, 220)
  line L26 (-42, 190) -> (-44.5465, 190)
  line L27 (-42, 220) -> (-42, 190)
  circle C1 centre (-37, 180) radius 1
  circle C2 centre (-37, 205) radius 1
  circle C3 centre (-37, 230) radius 1
  point P23 (-37, 205)
  point P3 (-37, 205)
  point P28 (-42, 205)
  point P29 (-42, 220)
  point P30 (-43, 220)
  point P31 (-43, 190)
  point P35 (-42, 190)
  coincident L15 P23
  coincident L16 P23
  coincident P3 P23
  horizontal L17
  vertical L18
  horizontal L19
  vertical L20
  midpoint L18 P28
  parallel L18 L21
  perpendicular L21 L22
  perpendicular L4 L23
  horizontal L24
  vertical L25
  horizontal L26
  vertical L27
  dimension "d1746" distance P28 P29 = 15
  dimension "d1747" distance P30 P31 = 30
  dimension "d1748" distance P29 P35 = 30
extrude "Extrude23" new body sketch "Sketch13" profile of C2 L17 L18 L19 L20 L21 L27 along normal blind 3
extrude "Extrude24" new body sketch "Sketch13" profile of L18 L21 L22 L23 L24 L25 L26 L27 along normal blind 21
combine "Combine9"
sketch "Sketch5" plane through (0, -68.6749, 252.2759) normal (0, 0.2627, -0.9649) x axis (-1, 0, 0)
  line L1 (22, -102.5732) -> (-130, -102.5732)
  line L2 (22, 3.5381) -> (22, -102.5732)
  line L3 (17, 3.5381) -> (22, 3.5381)
  line L4 (17, 126.1027) -> (17, 3.5381)
  line L5 (-77.3814, 126.1027) -> (17, 126.1027)
  line L6 (-77.3814, -93.8973) -> (-77.3814, 126.1027)
  line L7 (-97.3814, -93.8973) -> (-77.3814, -93.8973)
  line L8 (-97.3814, 126.1027) -> (-97.3814, -93.8973)
  line L9 (-125, 126.1027) -> (-97.3814, 126.1027)
  line L10 (-125, 3.5381) -> (-125, 126.1027)
  line L11 (-130, 3.5381) -> (-125, 3.5381)
  line L12 (-130, -102.5732) -> (-130, 3.5381)
  line L13 (-97.3814, 33) -> (-106, 33)
  line L14 (-97.3814, 29) -> (-97.3814, 33)
  line L15 (-106, 29) -> (-97.3814, 29)
  line L16 (-106, 33) -> (-106, 29)
  circle C1 centre (-71.0487, -84.4448) radius 1
  circle C2 centre (-71.0487, -95.757) radius 1
  circle C3 centre (-54, -84.4448) radius 1
  circle C4 centre (-101.5356, -88.0171) radius 1
  circle C5 centre (-54, -95.757) radius 1
  circle C6 centre (-101.5356, 117.6424) radius 1
  circle C7 centre (-101.5356, -50.4038) radius 1
  circle C8 centre (-54, -71.4746) radius 1
  circle C9 centre (-101.5356, -9.2833) radius 1
  circle C10 centre (-101.5356, 78.3036) radius 1
  circle C11 centre (-54, -52.5645) radius 1
  circle C12 centre (-54, -64) radius 1
  circle C13 centre (-101.5356, 31) radius 1
  point P27 (-106, 33)
  point P30 (-106, 29)
  horizontal L13
  vertical L14
  horizontal L15
  vertical L16
  dimension "d1753" distance P27 P30 = 4
extrude "Extrude25" add of existing geometry blind 3
sketch "Sketch6" plane through (0, -68.6749, 252.2759) normal (0, 0.2627, -0.9649) x axis (-1, 0, 0)
  line L1 (-69, -5) -> (-107, -5)
  line L2 (-69, -13) -> (-69, -5)
  line L3 (-107, -13) -> (-69, -13)
  line L4 (-107, -5) -> (-107, -13)
  line L5 (-77.3814, 129.1027) -> (-77.3814, -93.8973)
  line L6 (-97.3814, 129.1027) -> (-77.3814, 129.1027)
  line L7 (-97.3814, -93.8973) -> (-97.3814, 129.1027)
  line L8 (-77.3814, -93.8973) -> (-97.3814, -93.8973)
  line L9 (-77.7614, -5) -> (-97, -5)
  line L10 (-77.7614, -13) -> (-77.7614, -5)
  line L11 (-97, -13) -> (-77.7614, -13)
  line L12 (-97, -5) -> (-97, -13)
  point P12 (-77.7614, -13)
  point P10 (-97, -5)
  horizontal L1
  vertical L2
  horizontal L3
  vertical L4
  horizontal L9
  vertical L10
  horizontal L11
  vertical L12
  coincident L3 P12
  coincident L1 P10
extrude "Extrude5" new body sketch "Sketch6" profile of L1 L2 L3 L4 L5 L7 L9 L10 L11 L12 along normal blind 2
extrude "Extrude6" new body sketch "Sketch5" profile of C9 against normal blind 3
extrude "Extrude7" add sketch "Sketch6" profile of L1 L2 L3 L4 L5 L7 L9 L10 L11 L12 along normal blind 2
remove_instance "RemoveInstance1"
remove_instance "RemoveInstance2"
remove_instance "RemoveInstance3"
remove_instance "RemoveInstance4"
remove_instance "RemoveInstance5"
remove_instance "RemoveInstance1"
copy_paste "CutPaste1"
remove_instance "RemoveInstance2"
remove_instance "RemoveInstance3"
remove_instance "RemoveInstance4"
remove_instance "RemoveInstance5"
remove_instance "RemoveInstance6"
remove_body "RemoveBody5"
remove_body "RemoveBody5"
remove_instance "RemoveInstance17"
remove_instance "RemoveInstance18"
remove_instance "RemoveInstance19"
remove_instance "RemoveInstance20"
remove_instance "RemoveInstance21"
remove_instance "RemoveInstance22"
remove_instance "RemoveInstance23"
remove_instance "RemoveInstance24"
remove_body "RemoveBody21"
remove_body "RemoveBody22"
remove_body "RemoveBody23"
remove_body "RemoveBody24"
remove_body "RemoveBody25"
remove_body "RemoveBody26"
remove_body "RemoveBody27"
remove_instance "RemoveInstance1"
remove_instance "RemoveInstance1"
remove_instance "RemoveInstance2"
remove_instance "RemoveInstance1"
remove_instance "RemoveInstance2"
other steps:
derived_base_feature "Derived Base Feature1"
derived_base_feature "Derived Base Feature1"
derived_base_feature "Derived Base Feature1"
derived_base_feature "Derived Base Feature1"
base_feature "Base Feature1"
base_feature "Base Feature1" bodies "Roof"
base_feature "Base Feature1" bodies "S1_L_Pin"
derived_base_feature "Derived Base Feature1" bodies "Motor_End"
derived_base_feature "Derived Base Feature1"
derived_base_feature "Derived Base Feature1"
derived_base_feature "Derived Base Feature1"
derived_base_feature "Derived Base Feature1"
derived_base_feature "Derived Base Feature1"
derived_base_feature "Derived Base Feature1"
derived_base_feature "Derived Base Feature1"
derived_base_feature "Derived Base Feature1"
derived_base_feature "Derived Base Feature1"
derived_base_feature "Derived Base Feature1"
derived_base_feature "Derived Base Feature1"
derived_base_feature "Derived Base Feature1" sketch "Tests"
derived_base_feature "Derived Base Feature1"
derived_base_feature "Derived Base Feature1" sketch "Sketch6"
derived_base_feature "Derived Base Feature1"
extrude "Extrude1" cut sketch "Sketch6" profile of K3 A3 K4 A4 C1 C2 C3 C4 L1 A5 L2 K5 A6 A7 A8 A9 A10 L3 L4 L5 L6 L7 L8 L9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 against normal blind 240
move "Move1"
derived_base_feature "Derived Base Feature1"
extrude "Extrude1" cut sketch "Sketch6" profile of K3 A3 K4 A4 C1 C2 C3 C4 L1 A5 L2 K5 A6 A7 A8 A9 A10 L3 L4 L5 L6 L7 L8 L9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 against normal blind 240
extrude "Extrude2" cut of existing geometry blind -7
base_feature "Base Feature1" bodies "Left_Wall_Cap_Low", "Old_Left_Wall_Cap_Lower"
extrude "Extrude2" add sketch "Sketch13" profile of C1 C2 C3 C4 L1 L2 L3 L4 L5 L6 L7 L8 L17 L18 L19 L20 A6 A7 A8 A9 L21 L22 L23 L24 against normal blind 3
base_feature "Base Feature1" bodies "Right_Wall_Cap_Low (1)", "Handle_Exterior"
base_feature "Base Feature1"
base_feature "Base Feature1"
base_feature "Base Feature1" bodies "interior_motor_holder"
extrude "Extrude2" cut sketch "Sketch6" profile of K3 A3 K4 A4 C1 C2 C3 C4 L1 A5 L2 K5 A6 A7 A8 A9 A10 L3 L4 L5 L6 L7 L8 L9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 against normal blind 240
base_feature "Base Feature1" bodies "Left_Wall_Cap_Low"
base_feature "Base Feature2" bodies "Left_Wall_Cap_Low (1)", "Right_Wall_Cap_Low (1)"
extrude "Extrude2" cut sketch "Sketch2" against normal blind 7
extrude "Extrude1" cut sketch "Sketch6" profile of K3 A3 K4 A4 C1 C2 C3 C4 L1 A5 L2 K5 A6 A7 A8 A9 A10 L3 L4 L5 L6 L7 L8 L9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 against normal blind 240
base_feature "Base Feature3" bodies "Coil"
base_feature "Base Feature1"
base_feature "Base Feature2"
extrude "Extrude5" cut sketch "Sketch8" profile of C2 L2 L3 L4 L5 L6 L7 against normal blind 1
extrude "Extrude5" cut sketch "Sketch8" profile of C2 L2 L3 L4 L5 L6 L7 against normal blind 1
base_feature "Base Feature1" bodies "Coupling_testing"
base_feature "Base Feature1" bodies "Left_Wall_Cap_Low", "Left_Wall_Cap_Mid"
base_feature "Base Feature2" bodies "Left_Wall_Cap_Mid", "OLD_new_below_Lef_Wall_Cap_Upper"
extrude "Extrude25" cut sketch "Sketch33" profile of C1 C2 C3 C4 against normal blind 9
base_feature "Base Feature1" bodies "Back_wall"
base_feature "Base Feature1" bodies "Left_wall"
derived_base_feature "Derived Base Feature1"
derived_base_feature "Derived Base Feature2"
derived_base_feature "Derived Base Feature3" bodies "Base"
offset_faces "OffsetFaces1" distance 2
base_feature "Base Feature1" bodies "Left_Wall_Cap_Low", "Left_Wall_Cap_Mid"
base_feature "Base Feature2" bodies "Left_Wall_Cap_Mid", "Lef_Wall_Cap_Upper"
base_feature "Base Feature1" bodies "Right_wall_Final"
extrude "Extrude19" cut sketch "Sketch6" profile of K3 A3 K4 A4 C1 C2 C3 C4 L1 A5 L2 K5 A6 A7 A8 A9 A10 L3 L4 L5 L6 L7 L8 L9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 against normal blind 240
base_feature "Base Feature2" bodies "Right_wall"
base_feature "Base Feature3" bodies "LU_Tensor_holders", "LL_Tensor_holders (1) (1)"
base_feature "Base Feature4" bodies "LU_Tensor_holders (1)", "LU_Tensor_holders (1) (1)"
extrude "Extrude52" cut sketch "Sketch25" profile of L1 L2 L3 L4 L5 L6 L7 L8 A1 L9 A2 L10 A3 L11 A4 L12 L13 L14 L15 L16 L17 L18 L19 L20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 blind -24 from offset -3 bodies "Right_wall (1)", "Right_wall (2)"
extrude "Extrude56" cut of existing geometry blind -20
extrude "Extrude57" cut of existing geometry blind -10
extrude "Extrude58" cut of existing geometry blind -15
extrude "Extrude59" cut of existing geometry blind -15
extrude "Extrude60" cut of existing geometry blind -15
create_component "CreateComponent1"
create_component "CreateComponent2"
create_component "CreateComponent3"
create_component "CreateComponent5"
create_component "CreateComponent6"
remove_body "RemoveBody1"
create_component "CreateComponent7"
create_component "CreateComponent8"
remove_instance "RemoveInstance1"
remove_instance "RemoveInstance1"
create_component "CreateComponent10"
create_component "CreateComponent1"
create_component "CreateComponent11"
create_component "CreateComponent12"
create_component "CreateComponent13"
create_component "CreateComponent14"
remove_instance "RemoveInstance2"
remove_instance "RemoveInstance3"
remove_instance "RemoveInstance4"
remove_instance "RemoveInstance5"
remove_instance "RemoveInstance6"
remove_instance "RemoveInstance7"
remove_instance "RemoveInstance8"
remove_instance "RemoveInstance9"
remove_instance "RemoveInstance10"
create_component "CreateComponent1"
create_component "CreateComponent15"
remove_instance "RemoveInstance11"
create_component "CreateComponent1"
create_component "CreateComponent2"
create_component "CreateComponent4"
create_component "CreateComponent5"
create_component "CreateComponent18"
revolve "Revolve2" sketch "Sketch2" AlongAngle 360
create_component "CreateComponent19"
create_component "CreateComponent20"
create_component "CreateComponent2"
create_component "CreateComponent3"
remove_instance "RemoveInstance1"
create_component "CreateComponent7"
create_component "CreateComponent6"
create_component "CreateComponent21"
remove_instance "RemoveInstance14"
create_component "CreateComponent3"
create_component "CreateComponent7"
create_component "CreateComponent8"
create_component "CreateComponent9"
create_component "CreateComponent10"
create_component "CreateComponent11"
remove_body "RemoveBody1"
create_component "CreateComponent12"
remove_body "RemoveBody2"
remove_body "RemoveBody3"
create_component "CreateComponent8"
create_component "CreateComponent1"
create_component "CreateComponent13"
remove_body "RemoveBody2"
create_component "CreateComponent14"
create_component "CreateComponent22"
create_component "CreateComponent1"
create_component "CreateComponent1"
create_component "CreateComponent3"
create_component "CreateComponent4"
create_component "CreateComponent5"
create_component "CreateComponent6"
